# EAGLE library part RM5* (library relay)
Power Relay SCHRACK 2 pole 16 A, DC- or AC-coil Source: http://www.schrack.com/.. 5832.pdf
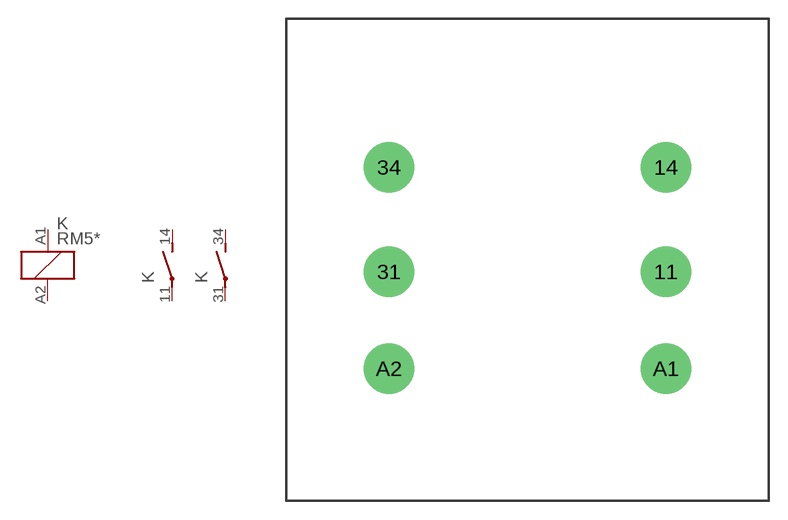
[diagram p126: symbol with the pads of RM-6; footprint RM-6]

Designator prefix K; gates 1=K 2=S 3=S

## RM507R06 (OC_FARNELL: unknown; OC_NEWARK: unknown), RM507R12 (OC_FARNELL: unknown; OC_NEWARK: unknown), RM507R24 (OC_FARNELL: unknown; OC_NEWARK: unknown), RM507R48 (OC_FARNELL: unknown; OC_NEWARK: unknown), RM507R60 (OC_FARNELL: unknown; OC_NEWARK: unknown), RM507S15 (OC_FARNELL: unknown; OC_NEWARK: unknown), RM507T30 (OC_FARNELL: unknown; OC_NEWARK: unknown), RM507V00 (OC_FARNELL: unknown; OC_NEWARK: unknown), RM507506 (OC_FARNELL: unknown; OC_NEWARK: unknown), RM507512 (OC_FARNELL: unknown; OC_NEWARK: unknown), RM507524 (OC_FARNELL: unknown; OC_NEWARK: unknown), RM507548 (OC_FARNELL: unknown; OC_NEWARK: unknown), RM507560 (OC_FARNELL: unknown; OC_NEWARK: unknown), RM507615 (OC_FARNELL: unknown; OC_NEWARK: unknown), RM507730 (OC_FARNELL: unknown; OC_NEWARK: unknown), RM507900 (OC_FARNELL: unknown; OC_NEWARK: unknown)  [RM-6]
11  2:P  pas
14  2:S  pas
31  3:P  pas
34  3:S  pas
A1  1:1  pas
A2  1:2  pas

## Footprint RM-6 (pad centres in mm)
Power Relay SCHRACK 2 pole 16 A, DC- or AC-coil Source: http://www.schrack.com/.. 5832.pdf
drill 2 pad 4 round: 11 11,-0.95; 14 11,7.35; 31 -11,-0.95; 34 -11,7.35; A1 11,-8.65; A2 -11,-8.65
